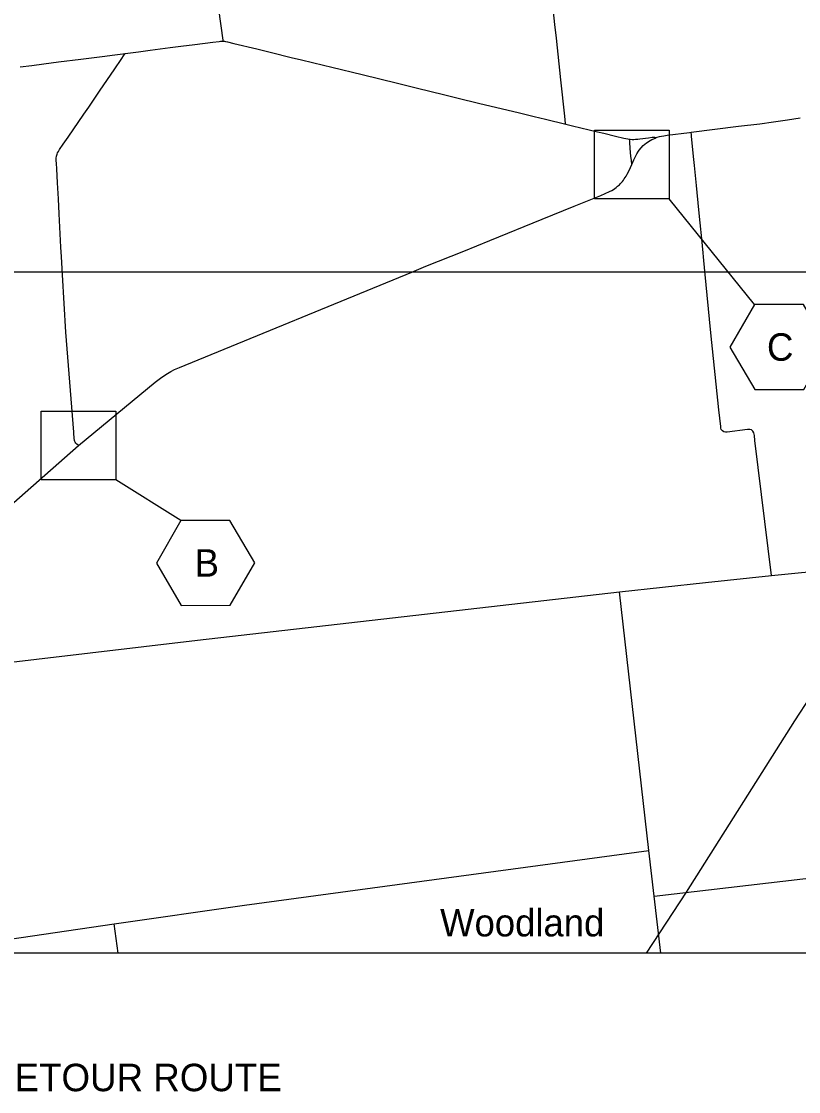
# Model space of a CAD drawing. Extents: x 0 to 680, y 0 to 440.
# Drawn here: x 252.8 to 332.1, y 124.6 to 233.7 of the extents above; entities that cross this region are included whole.
import ezdxf

# ---------------------------------------------------------------- set-up
doc = ezdxf.new("R2010")
doc.units = 0
for name, color, linetype in [('DV_X_County_Line', 7, 'Continuous'), ('GM_X_County_Road', 7, 'Continuous'), ('GM_X_State_Route', 7, 'Continuous'), ('GM_X_Township_Road', 7, 'Continuous'), ('GM_X_Unincorporated_Text', 7, 'Continuous'), ('RD_X_RR_2', 7, 'Continuous'), ('SH_Border', 7, 'Continuous'), ('SH_Text', 7, 'Continuous')]:
    doc.layers.add(name, color=color, linetype=linetype)

msp = doc.modelspace()

# ---------------------------------------------------------------- linework, layer by layer
at = {"layer": 'DV_X_County_Line'}
msp.add_line((399.36, 208.16), (30, 208.16), dxfattribs=at)
at = {"layer": 'GM_X_County_Road'}
msp.add_line((262.68, 138.72), (262.29, 141.71), dxfattribs=at)
for points in [[(273.4, 231.71), (273.38, 231.82), (273.35, 232.04), (273.22, 233.02), (273.07, 234.21), (272.92, 235.4), (272.74, 236.81), (272.46, 238.98), (272.14, 241.59), (271.79, 244.3), (271.58, 245.93), (271.36, 247.66), (271.15, 249.29), (270.8, 252), (270.53, 254.17), (270.08, 257.65), (270.04, 257.99)], [(263.4, 230.47), (263.67, 230.5), (264.75, 230.64), (265.94, 230.79), (268, 231.07), (269.09, 231.2), (270.5, 231.38), (272.34, 231.62), (273, 231.69), (273.11, 231.71), (273.2, 231.72), (273.3, 231.72), (273.4, 231.71)], [(273.4, 231.71), (273.43, 231.71), (273.54, 231.7), (273.64, 231.68), (273.85, 231.64), (274.49, 231.49), (276.83, 230.92), (278.32, 230.56), (280.34, 230.06), (281.4, 229.8), (283.63, 229.26), (284.48, 229.06), (287.57, 228.31), (291.18, 227.42), (293.2, 226.93), (295.85, 226.28), (297.23, 225.94), (299.57, 225.37), (301.16, 224.97), (303.61, 224.39), (305.1, 224.04), (306.27, 223.75), (308.32, 223.25)], [(252.71, 229.08), (253.9, 229.24), (255.1, 229.39), (256.62, 229.59), (258.89, 229.88), (261.06, 230.16), (262.36, 230.33), (262.91, 230.4), (263.4, 230.47)], [(257, 207.9), (256.97, 208.53), (256.91, 209.73), (256.85, 210.71), (256.68, 214.1), (256.6, 215.63), (256.5, 217.27), (256.43, 218.68), (256.39, 219.23), (256.37, 219.56), (256.38, 219.77), (256.4, 219.98), (256.46, 220.19), (256.51, 220.33), (256.6, 220.48), (256.71, 220.67), (257.09, 221.2), (257.6, 221.91), (259.2, 224.27), (259.69, 224.99), (260.86, 226.71), (262.28, 228.78), (263.08, 229.96), (263.24, 230.2), (263.4, 230.47)], [(308.32, 223.25), (309.03, 223.08), (311.58, 222.47), (312.22, 222.32), (313.39, 222.03), (314.24, 221.83), (314.45, 221.78), (314.67, 221.74), (314.83, 221.72)], [(314.83, 221.72), (314.89, 221.71), (315.11, 221.7), (315.27, 221.7), (315.44, 221.71), (315.67, 221.73), (315.88, 221.75), (316.75, 221.87), (317.14, 221.92), (317.23, 221.93), (317.32, 221.93), (317.41, 221.92), (317.56, 221.88)], [(315.06, 219.15), (315.02, 219.55), (314.97, 219.99), (314.91, 220.76), (314.86, 221.42), (314.85, 221.53), (314.83, 221.72)], [(258.65, 190.5), (258.49, 190.62), (258.38, 190.72), (258.3, 190.82), (258.27, 190.91), (258.25, 190.99), (258.22, 191.23), (258.18, 191.74), (258.18, 191.86), (257.34, 202.06), (257, 207.9)], [(246.72, 179.99), (247.37, 174.65), (247.71, 172.04), (248.09, 168.68), (248.13, 168.39), (248.18, 168.25), (248.32, 168.12), (248.56, 168.06), (248.87, 168.06), (270.78, 170.66), (313.8, 175.57), (322.56, 176.52), (329.32, 177.23), (332.35, 177.54), (334.92, 177.78)], [(318.01, 138.72), (317.33, 144.55), (316.8, 149.19), (313.8, 175.57)], [(241.88, 138.72), (262.29, 141.71), (275.58, 143.63), (287.35, 145.22), (316.8, 149.19)]]:
    msp.add_lwpolyline(points, dxfattribs=at)
at = {"layer": 'GM_X_State_Route'}
for p, q in [((327.56, 204.85), (318.87, 215.65)), ((269.09, 182.84), (262.46, 187))]:
    msp.add_line(p, q, dxfattribs=at)
for points in [[(292.62, 208.16), (294.07, 208.76), (297.92, 210.31), (300.58, 211.4), (305.92, 213.57), (309.17, 214.88), (311.9, 215.99), (312.8, 216.39), (313.01, 216.5), (313.19, 216.6), (313.46, 216.79), (313.62, 216.92), (313.8, 217.08), (313.92, 217.2), (314.1, 217.4), (314.21, 217.53), (314.3, 217.66), (314.48, 217.94), (314.59, 218.15), (314.78, 218.53), (315.06, 219.15), (315.27, 219.63), (315.56, 220.21), (315.73, 220.49), (315.82, 220.61), (316, 220.83), (316.23, 221.06), (316.56, 221.33), (316.92, 221.57), (317.11, 221.68), (317.31, 221.77), (317.43, 221.83), (317.56, 221.88), (317.66, 221.92), (317.87, 221.98), (318.08, 222.03), (318.34, 222.07), (318.67, 222.12), (320.95, 222.41), (321.11, 222.43), (325.94, 223.03), (328.11, 223.3), (329.51, 223.48), (330.93, 223.68), (331.57, 223.78), (332.22, 223.9)], [(215.14, 153.21), (231.31, 166.36), (232.44, 167.31), (234.23, 168.9), (246.72, 179.99), (251.21, 183.93), (258.65, 190.5), (266.46, 196.93), (267.15, 197.47), (267.72, 197.83), (268.06, 198.04), (268.44, 198.23), (268.93, 198.45), (292.62, 208.16)]]:
    msp.add_lwpolyline(points, dxfattribs=at)
for points in [[(332.56, 204.87), (327.56, 204.85), (325.07, 200.51), (327.59, 196.19), (332.59, 196.21), (335.07, 200.54)], [(274.09, 182.86), (269.09, 182.84), (266.61, 178.5), (269.12, 174.18), (274.12, 174.2), (276.61, 178.54)]]:
    msp.add_lwpolyline(points, close=True, dxfattribs=at)
at = {"layer": 'GM_X_Township_Road'}
msp.add_line((317.33, 144.55), (335.19, 146.63), dxfattribs=at)
for points in [[(308.32, 223.25), (308.31, 223.31), (308.22, 224.05), (307.83, 227.77), (307.39, 232.01), (307.23, 233.42), (306.95, 236.03), (306.57, 239.51), (306.42, 240.92), (306.3, 242.23), (305.98, 244.83), (305.78, 246.57), (305.14, 252.99), (304.8, 256.25), (304.38, 260.49), (304.18, 262.24)], [(322.51, 208.25), (322.37, 209.71), (322.33, 210.14), (322.19, 211.56), (322.03, 213.19), (321.9, 214.5), (321.65, 217.01), (321.49, 218.7), (321.45, 219.03), (321.36, 219.94), (321.15, 222.01), (321.14, 222.12), (321.11, 222.43)], [(329.32, 177.23), (327.61, 191), (327.56, 191.51), (327.51, 191.79), (327.41, 191.95), (327.25, 192.07), (327.09, 192.13), (326.87, 192.13), (324.79, 191.86), (324.61, 191.86), (324.46, 191.89), (324.31, 191.99), (324.19, 192.13), (324.15, 192.25), (324.13, 192.42), (323.94, 194.14), (323.12, 201.99), (322.51, 208.25)]]:
    msp.add_lwpolyline(points, dxfattribs=at)
at = {"layer": 'RD_X_RR_2'}
msp.add_lwpolyline([(316.55, 138.72), (320.64, 144.95), (331.67, 162.41), (334.88, 167.32)], dxfattribs=at)
at = {"layer": 'SH_Border'}
for points in [[(311.25, 222.65), (318.87, 222.65), (318.87, 215.65), (311.25, 215.65)], [(254.83, 194), (262.46, 194), (262.46, 187), (254.83, 187)]]:
    msp.add_lwpolyline(points, close=True, dxfattribs=at)
at = {"layer": 'SH_Text'}
msp.add_lwpolyline([(30, 430), (466.92, 430), (466.92, 291.27), (342.9, 138.72), (30, 138.72)], close=True, dxfattribs=at)

# ---------------------------------------------------------------- texts
at = {"layer": 'GM_X_State_Route'}
for s, p in [('C', (328.84, 199.13)), ('B', (270.48, 177.12))]:
    msp.add_text(s, height=2.8, dxfattribs=at).set_placement(p)
at = {"layer": 'GM_X_Unincorporated_Text'}
msp.add_text('Woodland', height=2.78, rotation=0, dxfattribs=at).set_placement((295.52, 140.44))
at = {"layer": 'SH_Text'}
msp.add_text('DESIGNATED LOCAL DETOUR ROUTE', height=2.8, dxfattribs=at).set_placement((210.72, 124.66))

doc.saveas('drawing.dxf')
